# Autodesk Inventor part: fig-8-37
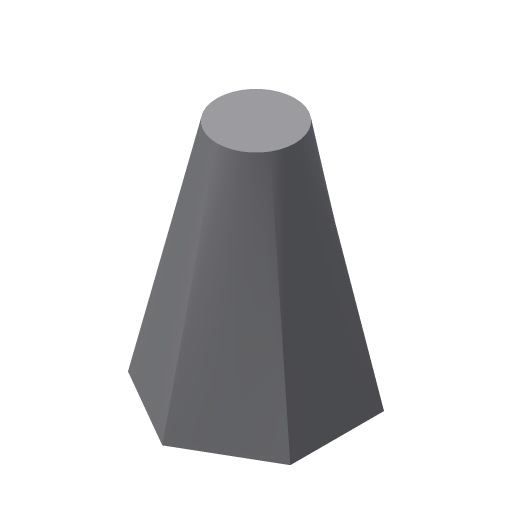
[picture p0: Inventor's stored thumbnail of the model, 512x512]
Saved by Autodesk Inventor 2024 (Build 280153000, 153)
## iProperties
Created: 2007-05
Part Number: fig-8-37
Document SubType Name: Modeling
Designer: Administrator
Density: 1 g/cm^3
Material: Generic
Appearance: Default
Author: Administrator
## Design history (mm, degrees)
sketch "Sketch1"
  geometry: L1 (0, 30)-(25.981, 15); L2 (25.981, 15)-(25.981, -15); L3 (25.981, -15)-(0, -30); L4 (0, -30)-(-25.981, -15); L5 (-25.981, -15)-(-25.981, 15); L6 (-25.981, 15)-(0, 30); 2 further points
  constraints: 12 end point, 1 coincident, 1 vertical, 14 other
workplane "Work Plane1"
sketch "Sketch2"
  geometry: C1 r 12.5 at (0, 0)
  constraints: 1 centre point, 1 other
sketch "Sketch3"
  geometry: L1 (0, 0)-(0, 75)
  constraints: 2 end point, 1 vertical, 1 other
loft "Loft1" dims "d5" = 0, "d6" = 90 deg, "d7" = 0, "d8" = 90 deg
body "Solid1"
other parameters: "d1" = 75
